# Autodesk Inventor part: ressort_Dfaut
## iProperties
Created: 2006-03
Part Number: ressort_Dfaut
Document SubType Name: Modeling
Designer: Flavien MARTY
Author: Flavien MARTY
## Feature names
1. Base1
